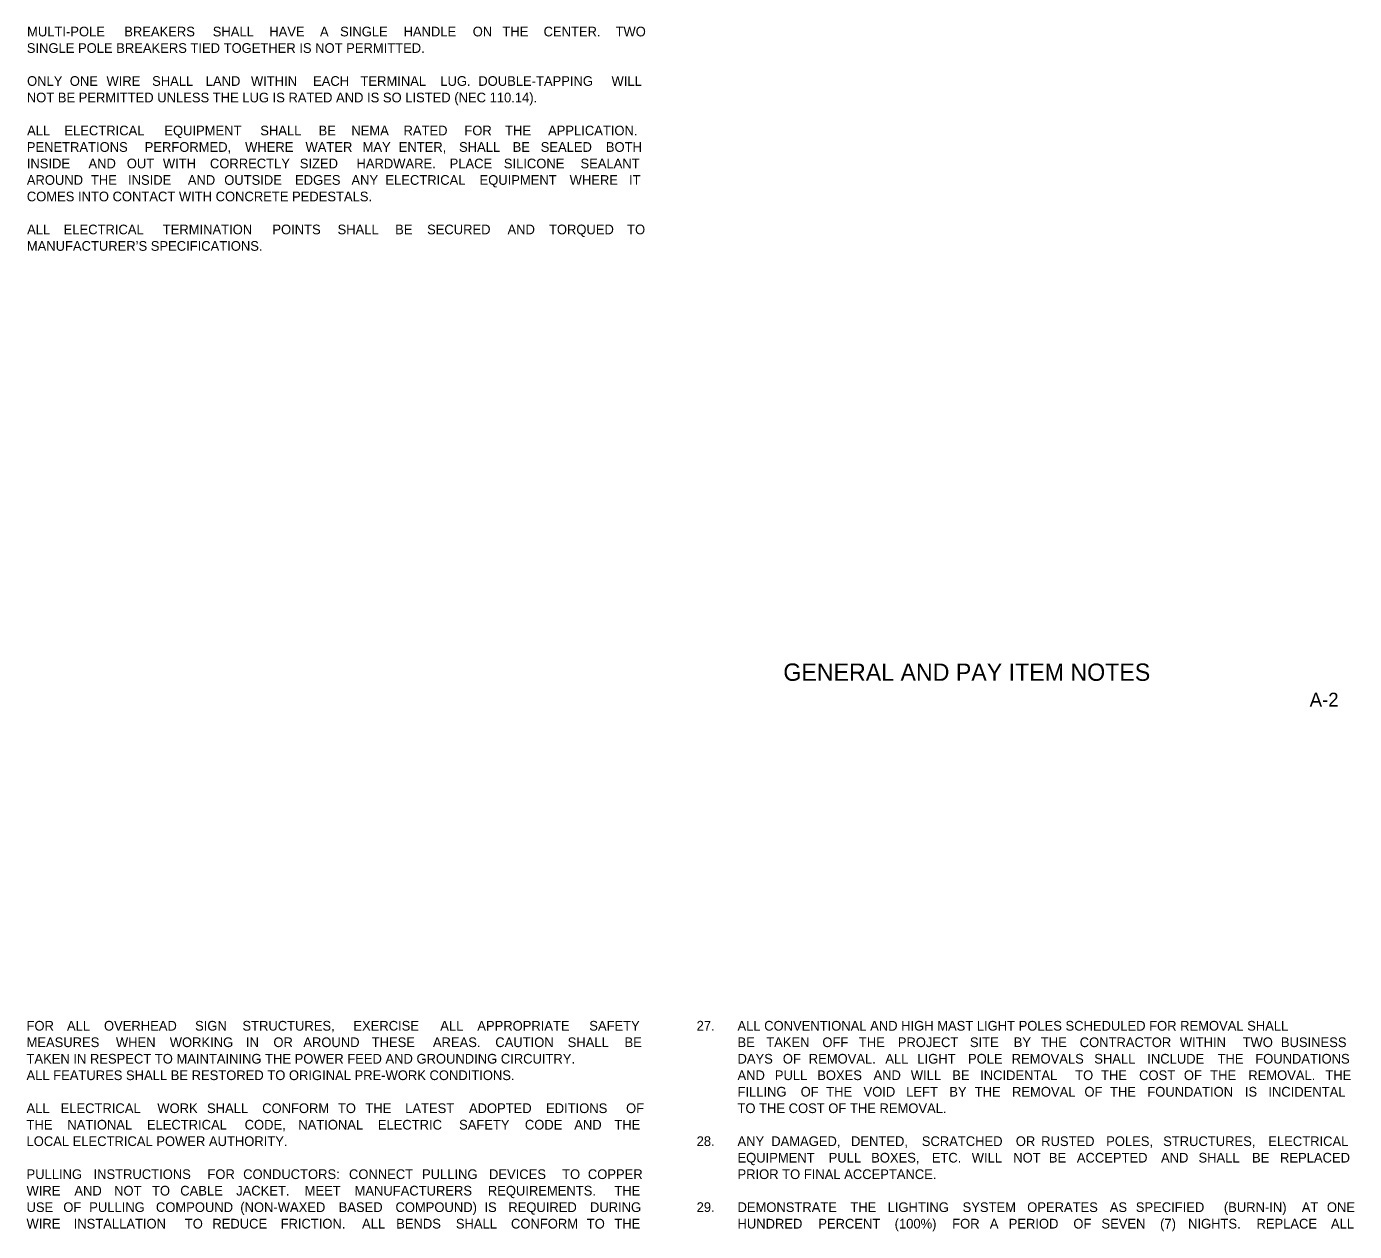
# Model space of a CAD drawing. Extents: x -55 to 2471539, y -90 to 3608906.
# Drawn here: x 568 to 1526, y 780 to 1649 of the extents above; entities that cross this region are included whole.
import ezdxf

# ---------------------------------------------------------------- set-up
doc = ezdxf.new("R2010")
doc.units = 0
for name, color, linetype in [('SheetLines_dp', 7, 'Continuous'), ('TextMisc', 7, 'Continuous'), ('XSCell', 7, 'Continuous')]:
    doc.layers.add(name, color=color, linetype=linetype)

msp = doc.modelspace()

# ---------------------------------------------------------------- texts
at = {"layer": 'SheetLines_dp'}
msp.add_text('A-2', height=10, dxfattribs=at).set_placement((1493.84, 1158.67))
at = {"layer": 'TextMisc'}
msp.add_text('GENERAL AND PAY ITEM NOTES ', height=12.5, dxfattribs=at).set_placement((1114.08, 1177.24))
at = {"layer": 'XSCell'}
for s, p in [('MULTI-POLE ', (568.41, 1642.24)), ('BREAKERS ', (638.51, 1642.24)), ('SHALL ', (702.38, 1642.24)), ('HAVE ', (743.16, 1642.24)), ('A ', (779.74, 1642.24)), ('SINGLE ', (794.27, 1642.24)), ('HANDLE ', (840.04, 1642.24)), ('ON ', (889.95, 1642.24)), ('THE ', (911.39, 1642.24)), ('CENTER. ', (941.09, 1642.24)), ('TWO ', (992.99, 1642.24)), ('SINGLE POLE BREAKERS TIED TOGETHER IS NOT PERMITTED.', (568.21, 1630.34)), ('ONLY ', (568.41, 1606.54)), ('ONE ', (599.23, 1606.54)), ('WIRE ', (625.7, 1606.54)), ('SHALL ', (658.63, 1606.54)), ('LAND ', (697.32, 1606.54)), ('WITHIN ', (729.93, 1606.54)), ('EACH ', (774.76, 1606.54)), ('TERMINAL ', (808.97, 1606.54)), ('LUG. ', (866.54, 1606.54)), ('DOUBLE-TAPPING ', (893.99, 1606.54)), ('WILL ', (990.11, 1606.54)), ('NOT BE PERMITTED UNLESS THE LUG IS RATED AND IS SO LISTED (NEC 110.14).', (568.21, 1594.64)), ('ALL ', (568.41, 1570.84)), ('ELECTRICAL ', (595.35, 1570.84)), ('EQUIPMENT ', (667.45, 1570.84)), ('SHALL ', (736.66, 1570.84)), ('BE ', (778.74, 1570.84)), ('NEMA ', (802.38, 1570.84)), ('RATED ', (840.02, 1570.84)), ('FOR ', (883.93, 1570.84)), ('THE ', (913.32, 1570.84)), ('APPLICATION. ', (944.32, 1570.84)), ('PENETRATIONS ', (568.21, 1558.94)), ('PERFORMED, ', (653.26, 1558.94)), ('WHERE ', (725.72, 1558.94)), ('WATER ', (769.3, 1558.94)), ('MAY ', (810.47, 1558.94)), ('ENTER, ', (836.56, 1558.94)), ('SHALL ', (880.09, 1558.94)), ('BE ', (918.76, 1558.94)), ('SEALED ', (938.99, 1558.94)), ('BOTH ', (986, 1558.94)), ('INSIDE ', (568.21, 1547.04)), ('AND ', (612.71, 1547.04)), ('OUT ', (640.35, 1547.04)), ('WITH ', (666.41, 1547.04)), ('CORRECTLY ', (700.34, 1547.04)), ('SIZED ', (765.18, 1547.04)), ('HARDWARE. ', (806.08, 1547.04)), ('PLACE ', (873.27, 1547.04)), ('SILICONE ', (912.4, 1547.04)), ('SEALANT ', (967.69, 1547.04)), ('AROUND ', (568.21, 1535.14)), ('THE ', (614.44, 1535.14)), ('INSIDE ', (641.25, 1535.14)), ('AND ', (684.38, 1535.14)), ('OUTSIDE ', (710.65, 1535.14)), ('EDGES ', (761.76, 1535.14)), ('ANY ', (802.44, 1535.14)), ('ELECTRICAL ', (826.96, 1535.14)), ('EQUIPMENT ', (894.87, 1535.14)), ('WHERE ', (959.89, 1535.14)), ('IT ', (1002.69, 1535.14)), ('COMES INTO CONTACT WITH CONCRETE PEDESTALS. ', (568.21, 1523.24)), ('ALL ', (568.41, 1499.44)), ('ELECTRICAL ', (594.79, 1499.44)), ('TERMINATION ', (666.33, 1499.44)), ('POINTS ', (745.4, 1499.44)), ('SHALL ', (792.42, 1499.44)), ('BE ', (833.95, 1499.44)), ('SECURED ', (857.02, 1499.44)), ('AND ', (915.06, 1499.44)), ('TORQUED ', (944.97, 1499.44)), ('TO ', (1001.35, 1499.44)), ('MANUFACTURER’S SPECIFICATIONS.', (568.21, 1487.54)), ('FOR ', (568.01, 924.84)), ('ALL ', (597.18, 924.84)), ('OVERHEAD ', (623.9, 924.84)), ('SIGN ', (689.63, 924.84)), ('STRUCTURES, ', (723.79, 924.84)), ('EXERCISE ', (803.84, 924.84)), ('ALL ', (866.52, 924.84)), ('APPROPRIATE ', (893.24, 924.84)), ('SAFETY ', (974.04, 924.84)), ('27.', (1051.5, 924.88)), ('ALL CONVENTIONAL AND HIGH MAST LIGHT POLES SCHEDULED FOR REMOVAL SHALL ', (1080.99, 924.84)), ('MEASURES ', (568.01, 912.94)), ('WHEN ', (632.51, 912.94)), ('WORKING ', (671.35, 912.94)), ('IN ', (726.33, 912.94)), ('OR ', (746.14, 912.94)), ('AROUND ', (767.73, 912.94)), ('THESE ', (817.07, 912.94)), ('AREAS. ', (861.21, 912.94)), ('CAUTION ', (906.23, 912.94)), ('SHALL ', (958.48, 912.94)), ('BE ', (999.48, 912.94)), ('BE ', (1080.99, 912.94)), ('TAKEN ', (1101.71, 912.94)), ('OFF ', (1142.24, 912.94)), ('THE ', (1168.55, 912.94)), ('PROJECT ', (1196.64, 912.94)), ('SITE ', (1248.68, 912.94)), ('BY ', (1280.31, 912.94)), ('THE ', (1299.83, 912.94)), ('CONTRACTOR ', (1327.91, 912.94)), ('WITHIN ', (1400.14, 912.94)), ('TWO ', (1445.44, 912.94)), ('BUSINESS ', (1473.05, 912.94)), ('TAKEN IN RESPECT TO MAINTAINING THE POWER FEED AND GROUNDING CIRCUITRY. ', (568.01, 901.04)), ('DAYS ', (1080.99, 901.04)), ('OF ', (1113.71, 901.04)), ('REMOVAL. ', (1132.4, 901.04)), ('ALL ', (1187.65, 901.04)), ('LIGHT ', (1210.77, 901.04)), ('POLE ', (1247.3, 901.04)), ('REMOVALS ', (1278.82, 901.04)), ('SHALL ', (1338.4, 901.04)), ('INCLUDE ', (1376.66, 901.04)), ('THE ', (1427.37, 901.04)), ('FOUNDATIONS ', (1454.55, 901.04)), ('ALL FEATURES SHALL BE RESTORED TO ORIGINAL PRE-WORK CONDITIONS.', (568.01, 889.14)), ('AND ', (1080.99, 889.14)), ('PULL ', (1107.94, 889.14)), ('BOXES ', (1138.52, 889.14)), ('AND ', (1179.11, 889.14)), ('WILL ', (1206.05, 889.14)), ('BE ', (1235.94, 889.14)), ('INCIDENTAL ', (1256.06, 889.14)), ('TO ', (1324.63, 889.14)), ('THE ', (1343.28, 889.14)), ('COST ', (1370.76, 889.14)), ('OF ', (1403.06, 889.14)), ('THE ', (1422.05, 889.14)), ('REMOVAL. ', (1449.54, 889.14)), ('THE ', (1505.1, 889.14)), ('FILLING ', (1080.99, 877.24)), ('OF ', (1126.56, 877.24)), ('THE ', (1144.99, 877.24)), ('VOID ', (1171.92, 877.24)), ('LEFT ', (1202.68, 877.24)), ('BY ', (1233.8, 877.24)), ('THE ', (1252.15, 877.24)), ('REMOVAL ', (1279.07, 877.24)), ('OF ', (1331.32, 877.24)), ('THE ', (1349.75, 877.24)), ('FOUNDATION ', (1376.68, 877.24)), ('IS ', (1447.07, 877.24)), ('INCIDENTAL ', (1464.02, 877.24)), ('ALL ', (568.01, 865.34)), ('ELECTRICAL ', (592.62, 865.34)), ('WORK ', (662.4, 865.34)), ('SHALL ', (698.26, 865.34)), ('CONFORM ', (738.02, 865.34)), ('TO ', (792.68, 865.34)), ('THE ', (812.52, 865.34)), ('LATEST ', (841.2, 865.34)), ('ADOPTED ', (887.23, 865.34)), ('EDITIONS ', (942.86, 865.34)), ('OF ', (1000.61, 865.34)), ('TO THE COST OF THE REMOVAL.', (1080.99, 865.34)), ('THE ', (568.01, 853.44)), ('NATIONAL ', (597.45, 853.44)), ('ELECTRICAL ', (654.85, 853.44)), ('CODE, ', (725.4, 853.44)), ('NATIONAL ', (764.08, 853.44)), ('ELECTRIC ', (821.48, 853.44)), ('SAFETY ', (880.07, 853.44)), ('CODE ', (927.59, 853.44)), ('AND ', (963.21, 853.44)), ('THE ', (992.12, 853.44)), ('LOCAL ELECTRICAL POWER AUTHORITY.', (568.01, 841.54)), ('28.', (1051.5, 841.58)), ('ANY ', (1080.99, 841.54)), ('DAMAGED, ', (1105.33, 841.54)), ('DENTED, ', (1162.91, 841.54)), ('SCRATCHED ', (1213.98, 841.54)), ('OR ', (1281.79, 841.54)), ('RUSTED ', (1300.09, 841.54)), ('POLES, ', (1347, 841.54)), ('STRUCTURES, ', (1388.11, 841.54)), ('ELECTRICAL ', (1463.99, 841.54)), ('EQUIPMENT ', (1080.99, 829.64)), ('PULL ', (1146.77, 829.64)), ('BOXES, ', (1177.43, 829.64)), ('ETC. ', (1221.17, 829.64)), ('WILL ', (1249.99, 829.64)), ('NOT ', (1279.96, 829.64)), ('BE ', (1305.64, 829.64)), ('ACCEPTED ', (1325.84, 829.64)), ('AND ', (1386.57, 829.64)), ('SHALL ', (1413.6, 829.64)), ('BE ', (1452.25, 829.64)), ('REPLACED ', (1472.45, 829.64)), ('PULLING ', (568.01, 817.74)), ('INSTRUCTIONS ', (616.36, 817.74)), ('FOR ', (698.53, 817.74)), ('CONDUCTORS: ', (724.3, 817.74)), ('CONNECT ', (800.66, 817.74)), ('PULLING ', (853.35, 817.74)), ('DEVICES ', (901.7, 817.74)), ('TO ', (954.47, 817.74)), ('COPPER ', (973.02, 817.74)), ('PRIOR TO FINAL ACCEPTANCE.', (1080.99, 817.74)), ('WIRE ', (568.01, 805.84)), ('AND ', (602.54, 805.84)), ('NOT ', (631.21, 805.84)), ('TO ', (658.53, 805.84)), ('CABLE ', (678.91, 805.84)), ('JACKET. ', (719.28, 805.84)), ('MEET ', (768.67, 805.84)), ('MANUFACTURERS ', (804.68, 805.84)), ('REQUIREMENTS. ', (900.84, 805.84)), ('THE ', (992.12, 805.84)), ('USE ', (568.01, 793.94)), ('OF ', (594.54, 793.94)), ('PULLING ', (613.24, 793.94)), ('COMPOUND ', (661.39, 793.94)), ('(NON-WAXED ', (722.22, 793.94)), ('BASED ', (793.21, 793.94)), ('COMPOUND) ', (834.21, 793.94)), ('IS ', (898.4, 793.94)), ('REQUIRED ', (915.62, 793.94)), ('DURING ', (974.54, 793.94)), ('29.', (1051.5, 793.98)), ('DEMONSTRATE ', (1080.99, 793.94)), ('THE ', (1162.41, 793.94)), ('LIGHTING ', (1189.29, 793.94)), ('SYSTEM ', (1243.4, 793.94)), ('OPERATES ', (1290.02, 793.94)), ('AS ', (1349.57, 793.94)), ('SPECIFIED ', (1368.37, 793.94)), ('(BURN-IN) ', (1431.91, 793.94)), ('AT ', (1488.15, 793.94)), ('ONE ', (1506.24, 793.94)), ('WIRE ', (568.01, 782.04)), ('INSTALLATION ', (602.03, 782.04)), ('TO ', (682.22, 782.04)), ('REDUCE ', (702.09, 782.04)), ('FRICTION. ', (751.31, 782.04)), ('ALL ', (810.1, 782.04)), ('BENDS ', (834.73, 782.04)), ('SHALL ', (877.78, 782.04)), ('CONFORM ', (917.56, 782.04)), ('TO ', (972.25, 782.04)), ('THE ', (992.12, 782.04)), ('HUNDRED ', (1080.99, 782.04)), ('PERCENT ', (1139.28, 782.04)), ('(100%) ', (1194.36, 782.04)), ('FOR ', (1235.9, 782.04)), ('A ', (1263.05, 782.04)), ('PERIOD ', (1276.66, 782.04)), ('OF ', (1323.31, 782.04)), ('SEVEN ', (1343.59, 782.04)), ('(7) ', (1385.9, 782.04)), ('NIGHTS. ', (1406.09, 782.04)), ('REPLACE ', (1455.44, 782.04)), ('ALL ', (1509.17, 782.04))]:
    msp.add_text(s, height=7, dxfattribs=at).set_placement(p)

doc.saveas('drawing.dxf')
